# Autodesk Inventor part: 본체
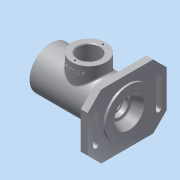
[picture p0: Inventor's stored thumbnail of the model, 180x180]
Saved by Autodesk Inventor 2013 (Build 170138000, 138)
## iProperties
Created: 2017-10
Part Number: 본체
Material: 알루미늄 6061
Document SubType Name: Modeling
Designer: Administrator
Density: 2.71 g/cm^3
Mass: 738.43 g
Surface Area: 652.241 cm^2
Volume: 272.484 cm^3
Author: Administrator
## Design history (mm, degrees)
sketch "스케치1"
  geometry: L1 (-58, 47)-(58, 47); L2 (58, 47)-(58, -47); L3 (58, -47)-(-58, -47); L4 (-58, -47)-(-58, 47); L5 (-50, 20)-(-50, -20); L6 (-42, -20)-(-42, 20); L7 (42, 20)-(42, -20); L8 (50, -20)-(50, 20); A1 r 4 centre (-46, -20) between (-50, -20) and (-42, -20); A2 r 4 centre (-46, 20) between (-42, 20) and (-50, 20); A3 r 4 centre (46, -20) between (42, -20) and (50, -20); A4 r 4 centre (46, 20) between (50, 20) and (42, 20); 5 further points
  constraints: 16 end point, 8 point on circle, 8 tangent, 5 horizontal alignment, 4 centre point, 4 midpoint, 4 vertical, 3 parallel, 1 equal radius, 1 horizontal, 1 perpendicular, 1 vertical alignment
  dimensions: "d0" = 116 distance of L1.start L1.end; "d2" = 94 distance of L1.end L2.end; "d3" = 46 horizontal distance of point (0, 0) A1.centre; "d4" = 46 horizontal distance of A3.centre point (0, 0); "d5" = 8 distance between parallel lines of L5 L6; "d6" = 40 distance of A1.centre A2.centre
extrude "돌출1" new body sketch "스케치1" distance "d7" = 10; taper "d8" = 0 deg
sketch "스케치2"
  geometry: C1 r 35 at (0, 0); 1 further point
  constraints: 1 centre point, 1 coincident
  dimensions: "d9" = 70 diameter of C1
extrude "돌출2" join sketch "스케치2" distance "d11" = 3; taper "d12" = 0 deg
sketch "스케치3"
  geometry: C1 r 31 at (0, 0); 1 further point
  constraints: 1 centre point, 1 coincident
  dimensions: "d13" = 62 diameter of C1
extrude "돌출3" join sketch "스케치3" distance "d14" = 102; taper "d15" = 0 deg
sketch "스케치4"
  geometry: L1 (-31, -102)-(31, -102) reference; C1 r 25 at (0, -46); 1 further point
  constraints: 1 centre point, 1 vertical alignment
  dimensions: "d16" = 56 distance from line of L1 C1.centre; "d17" = 50 diameter of C1
extrude "돌출4" join sketch "스케치4" distance "d18" = 47; taper "d19" = 0 deg
sketch "스케치5"
  geometry: L1 (35, 13)-(-35, 13) reference; L2 (-31, -102)-(31, -102) reference; L3 (0, 13)-(0, -102); L4 (16, -1)-(12.5, -1); L5 (12.5, -1)-(12.5, -8.3); L6 (12.5, -8.3)-(10, -8.3); L7 (10, -8.3)-(10, -11); L8 (10, -11)-(16.5, -11); L9 (16.5, -11)-(16.5, -16); L10 (16.5, -16)-(17.5, -16); L11 (17.5, -16)-(17.5, -27); L12 (17.5, -27)-(26, -27); L13 (26, -27)-(26, -65); L14 (26, -65)-(17.5, -65); L15 (17.5, -65)-(17.5, -76); L16 (17.5, -76)-(18.5, -76); L17 (18.5, -76)-(18.5, -77.75); L18 (18.5, -77.75)-(17.5, -77.75); L19 (17.5, -77.75)-(17.5, -81); L20 (17.5, -81)-(20, -81); L21 (20, -81)-(20, -90); L22 (20, -90)-(24, -90); L23 (24.101, -64.847)-(24, -64.847); L24 (24, -93)-(21, -93); L25 (21, -93)-(21, -102); L26 (16, -1)-(22, 13); L27 (24, -93)-(24, -90); 1 further point
  constraints: 50 end point, 10 horizontal, 10 vertical, 2 collinear, 2 midpoint, 2 point on line, 2 vertical alignment, 1 horizontal alignment, 1 perpendicular
  dimensions: "d21" = 52 diameter of L13 L3; "d24" = 32 diameter of L4.start L3; "d25" = 14 vertical distance of L4.start L26.end; "d26" = 25 diameter of L5 L3; "d27" = 20 diameter of L7 L3; "d28" = 33 diameter of L9 L3; "d29" = 35 diameter of L11 L3; "d30" = 37 diameter of L17 L3; "d31" = 40 diameter of L21 L3; "d32" = 48 diameter of L27 L3; "d33" = 42 diameter of L25 L3; "d35" = 2.7 distance of L6.end L7.end; "d36" = 5 distance of L8.end L9.end; "d40" = 3 distance of L24.start L22.end; "d43" = 1.75 distance of L16.end L17.end; "d61" = 44 diameter of L26.end L3; "d63" = 7.3 vertical distance of L4.start L5.end; "d96" = 12 distance from line of L22 L25.end; "d97" = 21 vertical distance of L25.end L20.end; "d98" = 26 distance from line of L25.end L16; "d99" = 38 distance of L12.end L13.end; "d100" = 11 distance of L10.end L11.end
revolve "회전1" sketch "스케치5" stored, may be unused: angle "d48" = 90 deg
hole "구멍1" diameter "d51" = 32; stored, may be unused: countersink angle "d55" = 90 deg, drill point angle "d57" = 118 deg; dims "d49" = 10, "d50" = 10, "d52" = 6, "d53" = 4, "d54" = 2, "d56" = 47
feature "스레드1" dims "d58" = 12, "d59" = 0
fillet "모깎기1" dims "d60" = 3
fillet "모깎기2" dims "d62" = 3
fillet "모깎기3" dims "d64" = 0.3
fillet "모깎기4" dims "d68" = 3
fillet "모깎기5" dims "d69" = 3
chamfer "모따기2" distance "d70" = 1; stored, may be unused: second distance "d71" = 2, angle "d72" = 30 deg
chamfer "모따기3" distance "d73" = 1; stored, may be unused: second distance "d74" = 2, angle "d75" = 30 deg
chamfer "모따기4" distance "d76" = 20; stored, may be unused: second distance "d77" = 2, angle "d78" = 30 deg
sketch "스케치6"
  geometry: L1 (0, -25)-(0, 25); L2 (31, 56)-(-31, 56) reference; 5 further points
  constraints: 2 end point, 2 horizontal alignment, 1 midpoint, 1 vertical, 1 vertical alignment, 3 other
  dimensions: "d79" = 56 distance from line of point (-20.5, 0) L2 (derived); "d80" = 20.5 distance of point (0, 0) point (-20.5, 0); "d81" = 20.5 distance of point (20.5, 0) point (0, 0)
hole "구멍2" sketch "스케치6" at (-20.5, 0), (20.5, 0) diameter "d82" = 2.459; stored, may be unused: countersink angle "d86" = 90 deg, drill point angle "d88" = 118 deg; dims "d83" = 6, "d84" = 4, "d85" = 2, "d87" = 8
fillet "모깎기6" dims "d95" = 3
node "작업 평면2"
sketch "스케치9"
  geometry: L1 (-47, -21)-(-47, -71) reference; L2 (-39, -44.77)-(-39, -47.23) reference; L3 (-22, -102)-(22, -102) reference; L4 (-34, -71)-(-47, -71) reference; 2 further points
  constraints: 1 other
  dimensions: "d104" = 56 distance from line of L3 point (-37, -46); "d105" = 10 distance from line of point (-37, -46) L1
feature "엠보싱2" sketch "스케치9" dims "d0" = 116, "d2" = 94, "d106" = 0.5, "d107" = 0
chamfer "모따기5" distance "d108" = 0.7; stored, may be unused: second distance "d109" = 2, angle "d110" = 30 deg
node "솔리드1"
other parameters: "d101" = -25
